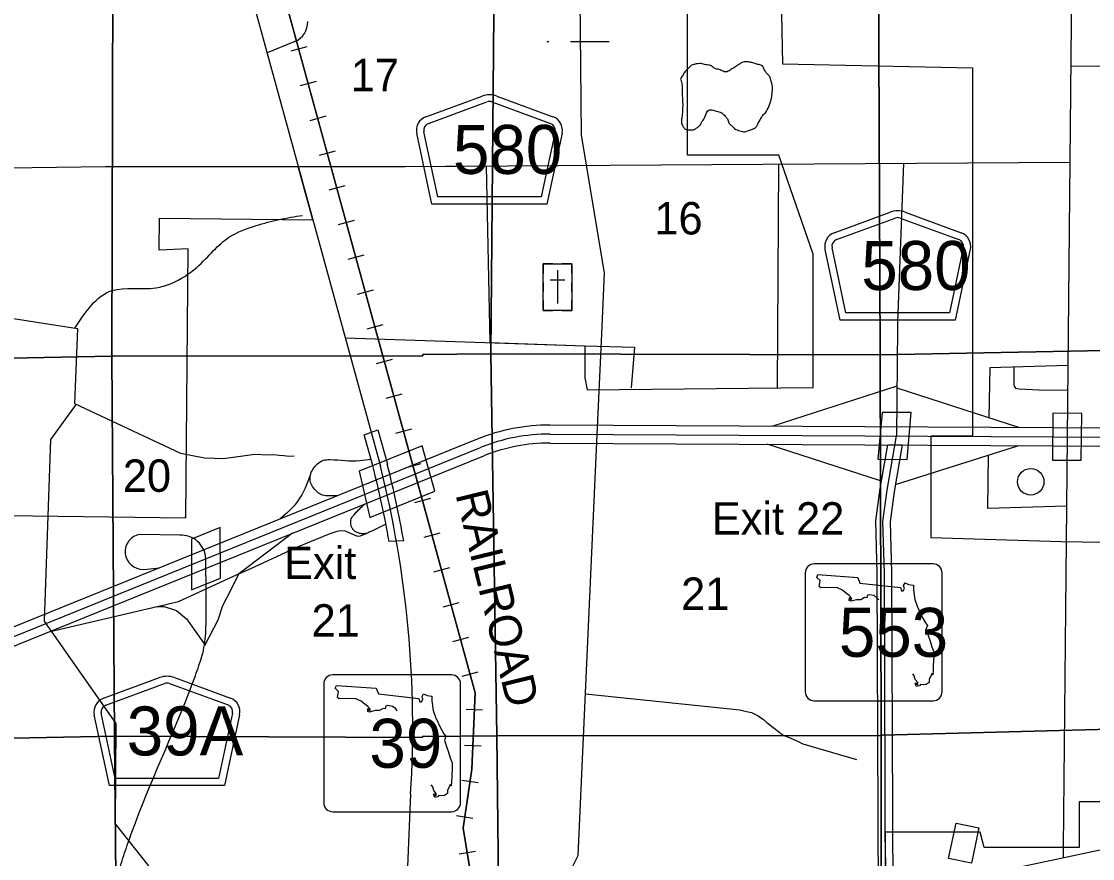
# Model space of a CAD drawing. Extents: x 380424 to 701066, y 1117407 to 1412949.
# Drawn here: x 610335 to 625205, y 1340370 to 1351991 of the extents above; entities that cross this region are included whole.
import ezdxf

# ---------------------------------------------------------------- set-up
doc = ezdxf.new("R2010")
doc.units = 0
for name, color, linetype in [('Cities Incorporated Area', 7, 'Continuous'), ('Connecting Roads', 7, 'Continuous'), ('County Routes Highway Center Lines', 7, 'Continuous'), ('Culture', 7, 'Continuous'), ('Interstate Divided Highway Outline and Fill', 7, 'Continuous'), ('Interstate Highway Center Lines', 7, 'Continuous'), ('Interstate Ramps', 7, 'Continuous'), ('Interstates Related Text', 7, 'Continuous'), ('Lakes and Ponds', 7, 'Continuous'), ('Local Roads Paved', 7, 'Continuous'), ('Local Roads Unimproved', 7, 'Continuous'), ('Masks for Road Features', 7, 'Continuous'), ('Narrow Canals', 7, 'Continuous'), ('Railroad Stations', 7, 'Continuous'), ('Railroads', 7, 'Continuous'), ('Railroads Text', 7, 'Continuous'), ('Roadshields County Roads', 7, 'Continuous'), ('Roadshilelds State Highways', 7, 'Continuous'), ('Section Lines', 7, 'Continuous'), ('Section Numbers', 7, 'Continuous'), ('State Route Divided Highway Outline and Fill', 7, 'Continuous'), ('State Routes Highway Center Lines', 7, 'Continuous'), ('Swamps', 7, 'Continuous'), ('Town Centers', 7, 'Continuous'), ('US Routes Highway Center Lines', 7, 'Continuous')]:
    doc.layers.add(name, color=color, linetype=linetype)

msp = doc.modelspace()

# ---------------------------------------------------------------- linework, layer by layer
at = {"layer": 'Cities Incorporated Area'}
for points in [[(620849, 1353936), (620901, 1351401), (623540, 1351348), (623540, 1346232), (622959, 1346235), (622959, 1344827), (624769, 1344772), (626231, 1344748)], [(610131, 1345134), (612616, 1345099), (612648, 1348835), (612247, 1348814), (612252, 1349262), (614381, 1349235), (614178, 1349978), (614466, 1349978), (615664, 1349978), (616785, 1349985), (616836, 1347532), (618157, 1347489), (618157, 1347044), (618188, 1346878), (621324, 1346911), (621324, 1348761), (620849, 1350134), (619582, 1350134), (619582, 1352721)], [(626390, 1341158), (625018, 1341158), (625018, 1340524), (623698, 1340524), (623646, 1340735), (622328, 1340735), (622333, 1339316), (632835, 1341367)]]:
    msp.add_lwpolyline(points, dxfattribs=at)
at = {"layer": 'Connecting Roads'}
msp.add_line((614830, 1347597), (618157, 1347489), dxfattribs=at)
msp.add_lwpolyline([(624838, 1344771), (624797, 1340524)], dxfattribs=at)
at = {"layer": 'County Routes Highway Center Lines'}
for points in [[(590572, 1349854), (592486, 1349845), (595800, 1349827), (599717, 1349836), (602453, 1349854), (603774, 1349871), (605408, 1349889), (606545, 1349915), (607507, 1349924), (609456, 1349950), (611502, 1349976), (614466, 1349978), (615664, 1349978), (624889, 1350037)], [(622579, 1350022), (622499, 1347818), (622497, 1347746), (622484, 1346238)]]:
    msp.add_lwpolyline(points, dxfattribs=at)
msp.add_spline([(611674, 1339519), (611674, 1339942), (611689, 1340153), (611768, 1340448), (611869, 1340738), (612698, 1342769), (612800, 1343050), (612862, 1343262), (612886, 1343418), (612901, 1343753), (612894, 1344533)], degree=3, dxfattribs=at)
at = {"layer": 'Culture'}
for p, q in [((617577, 1348627), (617577, 1348490)), ((617714, 1348627), (617577, 1348627)), ((617977, 1348627), (617839, 1348627)), ((617977, 1348490), (617977, 1348627)), ((617777, 1348540), (617777, 1348077)), ((617577, 1348365), (617577, 1348240)), ((617677, 1348402), (617877, 1348402)), ((617977, 1348240), (617977, 1348365)), ((617577, 1348115), (617577, 1347977)), ((617577, 1347977), (617714, 1347977)), ((617839, 1347977), (617977, 1347977)), ((617977, 1347977), (617977, 1348115))]:
    msp.add_line(p, q, dxfattribs=at)
msp.add_lwpolyline([(617577, 1348627), (617977, 1348627), (617977, 1347977), (617577, 1347977)], close=True, dxfattribs=at)
at = {"layer": 'Interstate Divided Highway Outline and Fill'}
for p, q in [((640619, 1346269), (617675, 1346387)), ((616663, 1346193), (609977, 1343486)), ((617674, 1346137), (640618, 1346019)), ((610070, 1343255), (616756, 1345961))]:
    msp.add_line(p, q, dxfattribs=at)
for radius in [2661, 2411]:
    msp.add_arc((617661, 1343726), radius, 89.705, 112.0402, dxfattribs=at)
at = {"layer": 'Interstate Highway Center Lines'}
for p, q in [((617674, 1346262), (640618, 1346144)), ((610023, 1343370), (616710, 1346077))]:
    msp.add_line(p, q, dxfattribs=at)
msp.add_arc((617661, 1343726), 2536, 89.705, 112.0402, dxfattribs=at)
at = {"layer": 'Interstate Ramps'}
for p, q in [((612532, 1344858), (611984, 1344871)), ((614100, 1344886), (613348, 1344318))]:
    msp.add_line(p, q, dxfattribs=at)
for points in [[(622490, 1346927), (620768, 1346372)], [(622489, 1346907), (624190, 1346354)], [(622275, 1345610), (620687, 1346122)], [(622470, 1345561), (624183, 1346104)], [(613270, 1344285), (613570, 1344418), (613948, 1344595), (614160, 1344694), (614519, 1344843), (614620, 1344882), (614675, 1344902), (614720, 1344915), (614763, 1344923), (614830, 1344919), (614920, 1344877), (615000, 1344846), (615043, 1344850), (615122, 1344884)], [(612028, 1344385), (612083, 1344387), (612254, 1344408)], [(610717, 1343516), (612514, 1343938), (613270, 1344285)], [(613348, 1344318), (613241, 1344103), (613128, 1343880), (613064, 1343680), (612875, 1343324)], [(612215, 1343868), (612316, 1343868), (612487, 1343815), (612626, 1343699), (612878, 1343345)]]:
    msp.add_lwpolyline(points, dxfattribs=at)
for centre, radius, start, end in [((612019, 1344629), 244, 98.0548, 272.2737), ((612553, 1344517), 342, 2.6623, 93.4015)]:
    msp.add_arc(centre, radius, start, end, dxfattribs=at)
for points in [[(614731, 1345411), (614560, 1345407), (614476, 1345433), (614418, 1345482), (614365, 1345553), (614343, 1345633), (614351, 1345713), (614396, 1345792), (614445, 1345850), (614529, 1345899), (614622, 1345908), (615034, 1345894), (615186, 1345920)], [(614349, 1345705), (614174, 1345336), (613928, 1345086)], [(615395, 1345013), (615171, 1344904), (615124, 1344885), (615079, 1344877), (615030, 1344885), (614988, 1344901), (614948, 1344927), (614925, 1344959), (614912, 1344990), (614907, 1345027), (614909, 1345069), (614922, 1345100), (614946, 1345134), (614969, 1345161), (615097, 1345290)]]:
    msp.add_spline(points, degree=3, dxfattribs=at)
at = {"layer": 'Lakes and Ponds'}
msp.add_spline([(619507, 1351014), (619492, 1351167), (619486, 1351188), (619513, 1351236), (619539, 1351283), (619592, 1351336), (619634, 1351378), (619676, 1351394), (619771, 1351405), (619835, 1351389), (619877, 1351384), (619919, 1351368), (619966, 1351336), (620009, 1351326), (620061, 1351305), (620119, 1351289), (620172, 1351315), (620225, 1351347), (620278, 1351384), (620315, 1351405), (620352, 1351426), (620383, 1351431), (620441, 1351426), (620505, 1351410), (620557, 1351394), (620610, 1351378), (620658, 1351305), (620689, 1351262), (620726, 1351220), (620737, 1351178), (620763, 1351088), (620758, 1351014), (620747, 1350925), (620742, 1350904), (620710, 1350809), (620663, 1350724), (620615, 1350671), (620600, 1350645), (620552, 1350555), (620505, 1350503), (620484, 1350497), (620378, 1350460), (620309, 1350471), (620236, 1350503), (620188, 1350550), (620156, 1350582), (620146, 1350613), (620135, 1350640), (620104, 1350677), (620061, 1350719), (620003, 1350740), (619935, 1350761), (619877, 1350761), (619829, 1350671), (619808, 1350634), (619787, 1350608), (619766, 1350566), (619740, 1350534), (619703, 1350508), (619666, 1350487), (619608, 1350487), (619550, 1350497), (619523, 1350529), (619497, 1350592), (619502, 1350650), (619507, 1351014)], degree=3, dxfattribs=at)
at = {"layer": 'Local Roads Paved'}
for p, q in [((614130, 1351712), (613746, 1351554)), ((620845, 1350011), (620826, 1346904)), ((618157, 1347489), (618847, 1347467))]:
    msp.add_line(p, q, dxfattribs=at)
for points in [[(625005, 1362017), (624852, 1346226), (624838, 1344771)], [(624902, 1351369), (626994, 1351374), (626999, 1350970)], [(624861, 1347216), (623777, 1347182), (623764, 1346493)], [(624112, 1347192), (624112, 1346951), (624117, 1346927), (624134, 1346900), (624185, 1346891), (624460, 1346876), (624858, 1346871)], [(624843, 1345261), (623753, 1345232), (623762, 1345971)], [(624797, 1340524), (624795, 1340379)]]:
    msp.add_lwpolyline(points, dxfattribs=at)
msp.add_arc((614020, 1351980), 290, 292.2845, 2.0691, dxfattribs=at)
at = {"layer": 'Local Roads Unimproved'}
msp.add_line((618847, 1347467), (618800, 1346904), dxfattribs=at)
at = {"layer": 'Masks for Road Features'}
for points in [[(622286, 1346564), (622225, 1345914), (622631, 1345912), (622686, 1346562)], [(624655, 1346552), (624649, 1345902), (625049, 1345900), (625055, 1346550)], [(615900, 1346100), (615026, 1345746), (615173, 1345105), (616073, 1345469)], [(612695, 1344802), (612698, 1344103), (613097, 1344264), (613094, 1344964)]]:
    msp.add_lwpolyline(points, close=True, dxfattribs=at)
at = {"layer": 'Narrow Canals'}
for points in [[(618241, 1332774), (618051, 1335427), (617930, 1337127), (617864, 1337538), (617566, 1339396), (617668, 1339615), (618062, 1340414), (618319, 1346053), (618397, 1347755), (618431, 1348503), (618108, 1350410), (618093, 1352318)], [(607794, 1345152), (607134, 1347294), (607224, 1347294), (607263, 1347304), (607345, 1347374), (608195, 1347954), (608274, 1348001), (608332, 1348065), (608416, 1348102), (608515, 1348116), (608590, 1348123), (611113, 1347727), (611070, 1346688), (612542, 1345996), (612875, 1345933), (613017, 1345928), (613139, 1345923), (613577, 1345986), (613756, 1345975), (613835, 1345981), (613914, 1345970), (613978, 1345965), (614051, 1345954), (614120, 1345960)], [(611095, 1346676), (610738, 1346186), (610653, 1343664), (610701, 1343590), (610759, 1343511), (611645, 1342245), (611635, 1340852), (612094, 1340272), (612099, 1339570)], [(618164, 1342656), (620309, 1342435), (620399, 1342414), (620468, 1342398), (620563, 1342351), (620636, 1342303), (620684, 1342261), (620747, 1342208), (620805, 1342166), (620895, 1342092), (620932, 1342076), (620995, 1342050), (621090, 1342008), (621185, 1341965), (621929, 1341744)]]:
    msp.add_lwpolyline(points, dxfattribs=at)
msp.add_spline([(611076, 1347733), (611593, 1348255), (612199, 1348292), (612416, 1348355), (612769, 1348577), (613002, 1348809), (613223, 1348999), (613592, 1349157), (613914, 1349241), (614236, 1349299)], degree=3, dxfattribs=at)
at = {"layer": 'Railroad Stations'}
msp.add_lwpolyline([(623207, 1340372), (623310, 1340862), (623628, 1340795), (623525, 1340305)], close=True, dxfattribs=at)
at = {"layer": 'Railroads'}
for p, q in [((614295, 1351638), (614073, 1351577)), ((614427, 1351156), (614205, 1351095)), ((614559, 1350674), (614337, 1350613)), ((614691, 1350191), (614469, 1350131)), ((614823, 1349709), (614601, 1349648)), ((614955, 1349227), (614733, 1349166)), ((615087, 1348745), (614866, 1348684)), ((615219, 1348262), (614998, 1348202)), ((615352, 1347780), (615130, 1347719)), ((615484, 1347298), (615262, 1347237)), ((615616, 1346816), (615394, 1346755)), ((615748, 1346333), (615526, 1346273)), ((615880, 1345851), (615658, 1345790)), ((616012, 1345369), (615790, 1345308)), ((616144, 1344887), (615922, 1344826)), ((616276, 1344405), (616055, 1344344)), ((616408, 1343922), (616187, 1343862)), ((616541, 1343440), (616319, 1343379)), ((616673, 1342958), (616451, 1342897)), ((616737, 1342432), (616507, 1342442)), ((616717, 1341933), (616487, 1341942)), ((616678, 1341423), (616450, 1341456)), ((616604, 1340928), (616377, 1340962)), ((616637, 1340470), (616410, 1340433))]:
    msp.add_line(p, q, dxfattribs=at)
for points in [[(622235, 1321266), (622209, 1329571), (622135, 1330167), (621486, 1330969), (619650, 1332653), (617866, 1334848), (617486, 1335317), (617186, 1336003), (616901, 1337860), (616753, 1339137), (616542, 1340340), (616468, 1340794), (616589, 1341612), (616632, 1342672), (612469, 1357868)], [(612731, 1356912), (614316, 1351125)], [(614316, 1351125), (615901, 1345339)], [(615901, 1345339), (616632, 1342672), (616589, 1341612), (616468, 1340794), (616542, 1340340), (616695, 1339466)]]:
    msp.add_lwpolyline(points, dxfattribs=at)
at = {"layer": 'Roadshields County Roads'}
for p, q in [((615950, 1350668), (616729, 1350954)), ((616936, 1350954), (617714, 1350668)), ((615985, 1350574), (616798, 1350873)), ((616867, 1350873), (617680, 1350574)), ((616034, 1349456), (615823, 1350438)), ((616115, 1349556), (615921, 1350459)), ((617743, 1350460), (617549, 1349556)), ((617841, 1350439), (617630, 1349456)), ((617630, 1349456), (616034, 1349456)), ((617549, 1349556), (616115, 1349556)), ((621617, 1349057), (622397, 1349343)), ((622603, 1349343), (623382, 1349057)), ((621652, 1348963), (622466, 1349262)), ((622535, 1349262), (623347, 1348963)), ((621701, 1347845), (621491, 1348827)), ((621782, 1347945), (621588, 1348848)), ((623410, 1348848), (623217, 1347945)), ((623508, 1348828), (623297, 1347845)), ((623297, 1347845), (621701, 1347845)), ((623217, 1347945), (621782, 1347945)), ((611473, 1342596), (612252, 1342882)), ((611507, 1342502), (612321, 1342801)), ((612390, 1342801), (613203, 1342503)), ((612459, 1342882), (613237, 1342596)), ((611557, 1341384), (611346, 1342366)), ((611638, 1341484), (611444, 1342387)), ((613266, 1342388), (613072, 1341484)), ((613364, 1342367), (613153, 1341384)), ((613072, 1341484), (611638, 1341484)), ((613153, 1341384), (611557, 1341384))]:
    msp.add_line(p, q, dxfattribs=at)
for centre, radius, start, end in [((616833, 1350673), 300, 69.8264, 110.1725), ((616833, 1350779), 100, 69.8265, 110.1725), ((616019, 1350480), 200, 110.1725, 192.0994), ((617645, 1350481), 200, 347.8996, 69.8265), ((616019, 1350480), 100, 110.1725, 192.0994), ((617645, 1350481), 100, 347.8996, 69.8265), ((622500, 1349061), 300, 69.827, 110.173), ((622500, 1349168), 100, 69.827, 110.173), ((621686, 1348869), 200, 110.173, 192.0999), ((623313, 1348869), 200, 347.9001, 69.827), ((621686, 1348869), 100, 110.173, 192.0999), ((623313, 1348869), 100, 347.9001, 69.827), ((612356, 1342601), 300, 69.827, 110.173), ((612356, 1342707), 100, 69.827, 110.173), ((611542, 1342408), 200, 110.173, 192.0999), ((611542, 1342408), 100, 110.173, 192.0999), ((613168, 1342409), 100, 347.9001, 69.827), ((613168, 1342409), 200, 347.9001, 69.827)]:
    msp.add_arc(centre, radius, start, end, dxfattribs=at)
at = {"layer": 'Roadshilelds State Highways'}
for p, q in [((622991, 1344461), (621341, 1344461)), ((621216, 1344336), (621216, 1342686)), ((623116, 1342686), (623116, 1344336)), ((616306, 1342921), (614656, 1342921)), ((614531, 1342796), (614531, 1341146)), ((616431, 1341146), (616431, 1342796)), ((621341, 1342561), (622991, 1342561)), ((614656, 1341021), (616306, 1341021))]:
    msp.add_line(p, q, dxfattribs=at)
for points in [[(622236, 1343962), (622216, 1343987), (622173, 1344024), (622104, 1344033), (622074, 1344020), (622071, 1343991), (622041, 1343994), (621989, 1343964), (621929, 1343964), (621854, 1343944), (621827, 1343951), (621831, 1343994), (621847, 1343964), (621863, 1343981), (621827, 1344024), (621771, 1344066), (621735, 1344096), (621662, 1344129), (621587, 1344132), (621432, 1344129), (621409, 1344146), (621422, 1344231), (621376, 1344274), (621392, 1344314)], [(621392, 1344314), (621946, 1344274), (621976, 1344195), (622539, 1344132), (622552, 1344086), (622576, 1344086), (622592, 1344119), (622582, 1344159), (622602, 1344198), (622651, 1344175), (622717, 1344165), (622717, 1344103), (622737, 1343967), (622770, 1343872), (622839, 1343723), (622885, 1343644), (622912, 1343608), (622892, 1343552), (622918, 1343483), (622951, 1343387), (622974, 1343308), (623001, 1343239), (623001, 1343176), (622994, 1343051), (622991, 1342978), (622988, 1342922), (622974, 1342938), (622958, 1342902), (622935, 1342863), (622935, 1342816), (622895, 1342787), (622852, 1342780), (622816, 1342787), (622803, 1342767), (622760, 1342760), (622740, 1342797), (622750, 1342813), (622763, 1342790), (622780, 1342783), (622780, 1342813), (622744, 1342856), (622730, 1342909), (622708, 1342933)], [(615551, 1342422), (615531, 1342447), (615488, 1342483), (615419, 1342493), (615390, 1342480), (615386, 1342450), (615357, 1342453), (615304, 1342424), (615244, 1342424), (615169, 1342404), (615142, 1342411), (615146, 1342453), (615162, 1342424), (615179, 1342440), (615142, 1342483), (615086, 1342526), (615050, 1342556), (614977, 1342589), (614902, 1342592), (614747, 1342589), (614724, 1342605), (614737, 1342691), (614691, 1342734), (614707, 1342773)], [(614707, 1342773), (615261, 1342734), (615291, 1342655), (615854, 1342592), (615868, 1342546), (615891, 1342546), (615907, 1342579), (615897, 1342618), (615917, 1342658), (615966, 1342635), (616032, 1342625), (616032, 1342562), (616052, 1342427), (616085, 1342331), (616154, 1342183), (616200, 1342104), (616227, 1342068), (616207, 1342011), (616233, 1341942), (616266, 1341847), (616289, 1341767), (616316, 1341698), (616316, 1341635), (616309, 1341510), (616306, 1341438), (616303, 1341382), (616289, 1341398), (616273, 1341362), (616250, 1341322), (616250, 1341276), (616210, 1341246), (616167, 1341240), (616131, 1341246), (616118, 1341227), (616075, 1341220), (616055, 1341256), (616065, 1341273), (616078, 1341250), (616095, 1341243), (616095, 1341273), (616059, 1341316), (616046, 1341368), (616023, 1341393)]]:
    msp.add_lwpolyline(points, dxfattribs=at)
for centre, start, end in [((621341, 1344336), 89.9995, 179.9995), ((622991, 1344336), 359.9995, 89.9995), ((614656, 1342796), 89.9992, 179.9992), ((616306, 1342796), 359.9992, 89.9992), ((621341, 1342686), 179.9995, 269.9995), ((622991, 1342686), 269.9995, 359.9995), ((614656, 1341146), 179.9992, 269.9992), ((616306, 1341146), 269.9992, 359.9992)]:
    msp.add_arc(centre, 125, start, end, dxfattribs=at)
at = {"layer": 'Section Lines'}
for points in [[(616897, 1352622), (616850, 1347376), (615907, 1347366), (615907, 1347351), (611603, 1347346), (611588, 1347345), (611606, 1352570), (615913, 1352607), (615913, 1352635)], [(622232, 1352673), (622257, 1347378), (622257, 1347363), (622249, 1347363), (616850, 1347376), (616897, 1352622)], [(627468, 1352710), (627536, 1347466), (622257, 1347363), (622257, 1347378), (622232, 1352673)], [(611606, 1352570), (611588, 1347345), (606420, 1347243), (606410, 1347243), (606410, 1347249), (606397, 1352568), (606397, 1352574)], [(616850, 1347376), (616933, 1342074), (615902, 1342065), (615902, 1342051), (611626, 1342068), (611588, 1347345), (611603, 1347346), (615907, 1347351), (615907, 1347366)], [(622257, 1347363), (622272, 1342081), (616933, 1342074), (616850, 1347376), (622249, 1347363)], [(627536, 1347466), (627536, 1347456), (627567, 1342232), (627566, 1342224), (622282, 1342082), (622272, 1342081), (622257, 1347363)], [(611588, 1347345), (611626, 1342068), (606428, 1341967), (606410, 1347243), (606420, 1347243)], [(627566, 1342224), (627590, 1336901), (622275, 1336815), (622267, 1336815), (622272, 1342081), (622282, 1342082)], [(611626, 1342068), (611626, 1342060), (611677, 1336696), (606369, 1336614), (606362, 1336613), (606428, 1341967)], [(616933, 1342074), (616994, 1336765), (615894, 1336762), (615894, 1336737), (611677, 1336696), (611626, 1342060), (611626, 1342068), (615902, 1342051), (615902, 1342065)], [(622272, 1342081), (622267, 1336815), (616994, 1336765), (616933, 1342074)]]:
    msp.add_lwpolyline(points, close=True, dxfattribs=at)
at = {"layer": 'State Route Divided Highway Outline and Fill'}
msp.add_line((615642, 1344780), (615440, 1344773), dxfattribs=at)
msp.add_lwpolyline([(615221, 1345792), (615095, 1346254), (615284, 1346321), (615415, 1345844), (615415, 1345842)], dxfattribs=at)
msp.add_lwpolyline([(622564, 1346112), (622453, 1345463), (622395, 1345046), (622415, 1344335), (622431, 1339876), (622231, 1339833), (622215, 1344332), (622194, 1345057), (622257, 1345509), (622361, 1346113)], close=True, dxfattribs=at)
for radius, start, end in [(14697, 10.088, 14.1518), (14897, 9.9809, 14.1558)]:
    msp.add_arc((600970, 1342198), radius, start, end, dxfattribs=at)
at = {"layer": 'State Routes Highway Center Lines'}
for p, q in [((612147, 1357388), (615318, 1345817)), ((615738, 1341267), (615628, 1338682))]:
    msp.add_line(p, q, dxfattribs=at)
msp.add_lwpolyline([(622331, 1339854), (622315, 1344333), (622295, 1345051), (622355, 1345486), (622484, 1346238)], dxfattribs=at)
msp.add_arc((600970, 1342198), 14797, 356.3921, 14.1558, dxfattribs=at)
at = {"layer": 'Swamps'}
for points in [[(617630, 1351712), (617658, 1351712)], [(617958, 1351712), (618494, 1351712)]]:
    msp.add_lwpolyline(points, dxfattribs=at)
at = {"layer": 'Town Centers'}
msp.add_circle((624346, 1345601), 184, dxfattribs=at)
at = {"layer": 'US Routes Highway Center Lines'}
msp.add_lwpolyline([(640903, 1343667), (625376, 1340503), (621563, 1339691)], dxfattribs=at)

# ---------------------------------------------------------------- texts
at = {"layer": 'Interstates Related Text'}
for s, p in [('Exit 22', (619919, 1344867)), ('Exit ', (613981, 1344251)), ('  21', (614029, 1343451))]:
    msp.add_text(s, height=450, dxfattribs=at).set_placement(p)
at = {"layer": 'Railroads Text'}
msp.add_text('RAILROAD', height=450, rotation=283.807, dxfattribs=at).set_placement((616358, 1345427))
at = {"layer": 'Roadshields County Roads'}
msp.add_text('580', height=680, rotation=359.9995, dxfattribs=at).set_placement((616326, 1349874))
for s, p in [('580', (621994, 1348263)), ('39A', (611797, 1341802))]:
    msp.add_text(s, height=680, dxfattribs=at).set_placement(p)
at = {"layer": 'Roadshilelds State Highways'}
for s, rotation, p in [('553', 359.9995, (621683, 1343171)), ('39', 359.9992, (615166, 1341631))]:
    msp.add_text(s, height=680, rotation=rotation, dxfattribs=at).set_placement(p)
at = {"layer": 'Section Numbers'}
for s, p in [('17', (614907, 1351022)), ('16', (619122, 1349034)), ('20', (611743, 1345461)), ('21', (619493, 1343822))]:
    msp.add_text(s, height=450, dxfattribs=at).set_placement(p)

doc.saveas('drawing.dxf')
